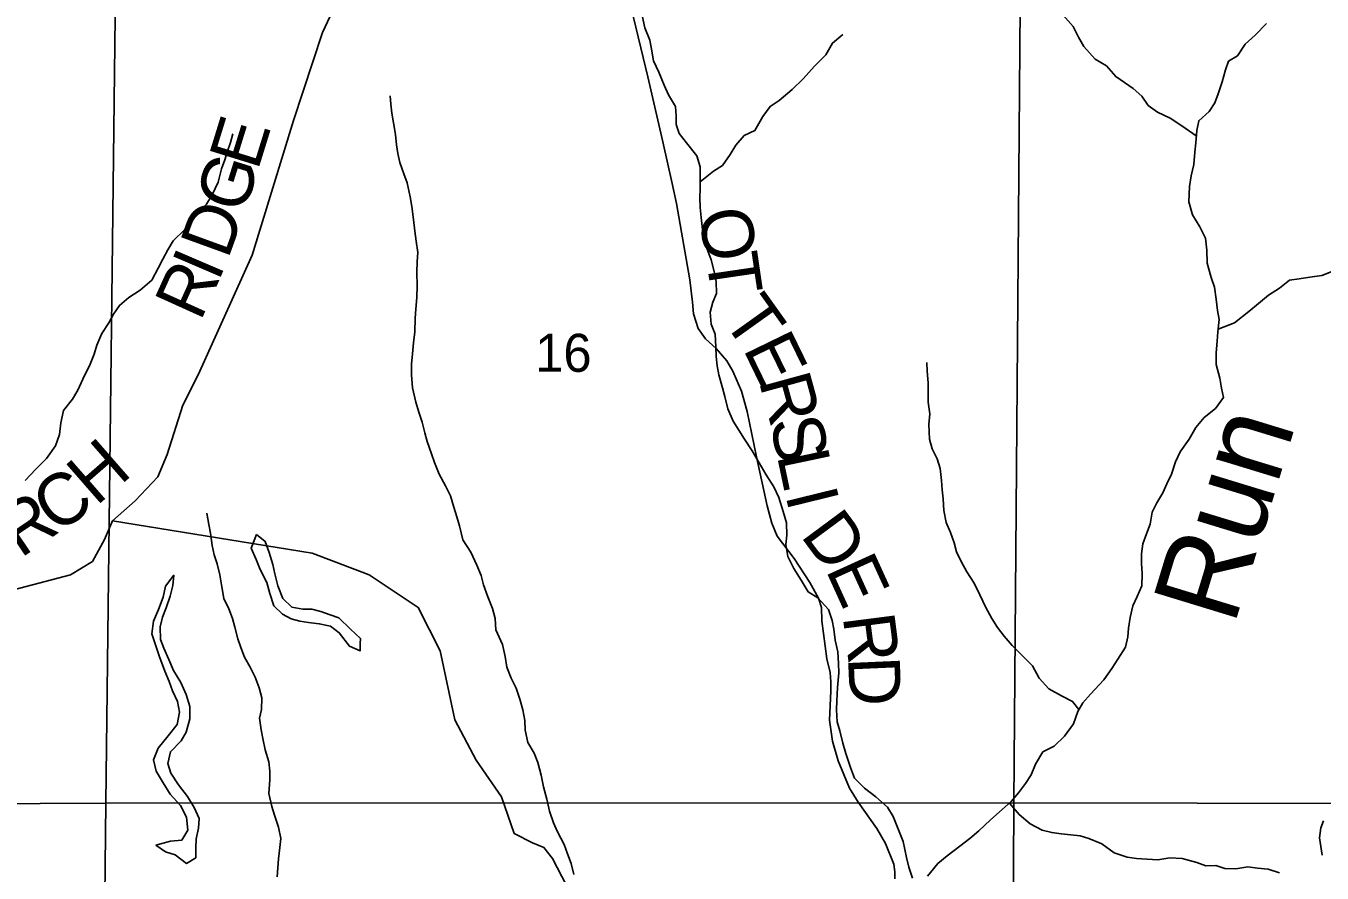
# Model space of a CAD drawing. Extents: x 2043100 to 2470832, y 443715 to 810583.
# Drawn here: x 2269120 to 2276651, y 621804 to 626725 of the extents above; entities that cross this region are included whole.
import ezdxf

# ---------------------------------------------------------------- set-up
doc = ezdxf.new("R2010")
doc.units = 0
for name, color, linetype in [('GM_X_County_Road', 7, 'Continuous'), ('GM_X_County_Road_Text', 7, 'Continuous'), ('GM_X_Minor_Lake', 7, 'Continuous'), ('GM_X_Minor_River', 7, 'Continuous'), ('GM_X_Minor_River_Text', 7, 'Continuous'), ('GM_X_Section', 7, 'Continuous'), ('GM_X_Section_Text', 7, 'Continuous'), ('GM_X_Township_Road', 7, 'Continuous'), ('GM_X_Township_Road_Text', 7, 'Continuous'), ('GM_X_Township_ROW', 7, 'Continuous')]:
    doc.layers.add(name, color=color, linetype=linetype)

msp = doc.modelspace()

# ---------------------------------------------------------------- linework, layer by layer
at = {"layer": 'GM_X_County_Road'}
msp.add_lwpolyline([(2274168.1, 621770.9), (2274169.4, 621811), (2274162.6, 621855), (2274114.4, 621976.4), (2274064.9, 622061.7), (2273956.1, 622216), (2273904.7, 622297.3), (2273839.8, 622456.5), (2273805.8, 622570.1), (2273789.6, 622692.1), (2273796.6, 622860.6), (2273797.6, 622914.7), (2273792.6, 622968.7), (2273773.2, 623048.5), (2273745.3, 623268.5), (2273741.9, 623346.6), (2273724.9, 623400.4), (2273675.3, 623491.7), (2273582.8, 623630.3), (2273484.4, 623760.8), (2273453.1, 623836.4), (2273427.3, 623938.1), (2273364.2, 624221.6), (2273311.5, 624485.2), (2273277.3, 624602.8), (2273227.2, 624720.2), (2273192.2, 624779.6), (2273130.9, 624850.7), (2273067.9, 624907.6), (2273026.8, 624967), (2272999.3, 625052.7), (2272992, 625120.7), (2272977.7, 625250.7), (2272899.8, 625694.2), (2272875.7, 625810), (2272821.4, 626051.5), (2272732.6, 626428.7), (2272637.4, 626829.8)], dxfattribs=at)
at = {"layer": 'GM_X_Minor_Lake'}
for points in [[(2270458.9, 623770.8), (2270429.2, 623690.6), (2270457.5, 623624.6), (2270481.8, 623566.6), (2270520.3, 623492.7), (2270536.6, 623428.6), (2270561, 623356.6), (2270611.3, 623308.8), (2270661.6, 623281), (2270711.7, 623267.2), (2270761.9, 623259.4), (2270824.1, 623251.7), (2270890.3, 623237.9), (2270940.6, 623200.1), (2270999.1, 623122.2), (2271061.4, 623094.5), (2271062.4, 623137.2)], [(2271062.4, 623137.2), (2271063.1, 623166.6), (2271006.7, 623220.4), (2270938.2, 623286.2), (2270888, 623304), (2270833.8, 623323.8), (2270781.6, 623337.6), (2270729.5, 623337.3), (2270665.3, 623349.1), (2270612.9, 623398.9), (2270584.5, 623472.9), (2270566.2, 623542.9), (2270553.9, 623597), (2270533.5, 623667), (2270509.2, 623731), (2270458.9, 623770.8)], [(2270072.4, 622749.4), (2270072.3, 622771.5), (2270051.9, 622841.5), (2270019.5, 622911.5), (2269977.1, 622981.4), (2269950.8, 623045.4), (2269920.4, 623109.4), (2269902.1, 623161.4), (2269899.8, 623233.5), (2269913.6, 623289.6), (2269935.4, 623343.8), (2269957.2, 623412), (2269973, 623474.2), (2269978.7, 623534.3), (2269930.9, 623470), (2269917.1, 623405.8), (2269889.3, 623335.6), (2269861.6, 623267.3), (2269851.9, 623193.2), (2269872.2, 623129.2), (2269896.6, 623059.2), (2269927, 622977.2), (2269951.3, 622917.2), (2269971.6, 622863.2), (2270000, 622801.2), (2270012.3, 622739.2), (2269998.6, 622667), (2269946.7, 622600.7), (2269888.9, 622530.3), (2269861.1, 622462.1), (2269877.4, 622396), (2269917.8, 622328.1), (2269958.2, 622262.2), (2270018.7, 622196.4), (2270053.1, 622128.4), (2270061.4, 622052.3), (2270025.6, 621994.1), (2269959.4, 621989.8), (2269875.3, 621965.4)], [(2269875.3, 621965.4), (2269931.6, 621927.5), (2269987.9, 621909.8), (2270052.2, 621860), (2270106.2, 621892.3), (2270108, 621950.4), (2270109.8, 622002.5), (2270123.5, 622064.6), (2270127.3, 622120.7), (2270096.9, 622184.7), (2270058.6, 622248.6), (2270006.1, 622316.5), (2269961.7, 622384.4), (2269945.4, 622440.4), (2269959.2, 622508.6), (2270021, 622571), (2270050.9, 622623.2), (2270072.6, 622699.4), (2270072.4, 622749.4)]]:
    msp.add_lwpolyline(points, dxfattribs=at)
at = {"layer": 'GM_X_Minor_River'}
for points in [[(2274271.3, 621774.7), (2274249, 621838.7), (2274236.7, 621894.8), (2274216.3, 621986.8), (2274185.8, 622064.8), (2274159.5, 622132.8), (2274125.2, 622186.7), (2274058.7, 622246.5), (2273992.3, 622296.3), (2273933.9, 622354.2), (2273911.6, 622416.2), (2273883.2, 622498.2), (2273866.9, 622558.2), (2273848.5, 622630.2), (2273834.3, 622682.2), (2273829.9, 622752.3), (2273831.7, 622804.4), (2273835.4, 622882.5), (2273843, 622966.7), (2273840.8, 623020.8), (2273836.5, 623088.9), (2273822.1, 623156.9), (2273813.8, 623221), (2273803.6, 623271), (2273783.3, 623335), (2273720.8, 623402.8), (2273664.5, 623436.7), (2273624.1, 623504.6), (2273581.7, 623572.5), (2273547.3, 623642.4), (2273535, 623712.5), (2273540.7, 623766.6), (2273538.4, 623838.7), (2273520.1, 623904.7), (2273493.7, 623984.7), (2273465.3, 624046.7), (2273420.9, 624116.6), (2273340.1, 624256.4), (2273295.7, 624324.3), (2273261.4, 624376.3), (2273229.1, 624428.2), (2273198.7, 624500.2), (2273180.3, 624572.2), (2273168, 624622.2), (2273145.7, 624698.2), (2273135.4, 624750.3), (2273131.2, 624804.3), (2273128.9, 624860.4), (2273124.6, 624934.5), (2273102.3, 624992.5), (2273095.9, 625062.6), (2273111.7, 625120.7), (2273131.5, 625170.9), (2273131.2, 625241), (2273119, 625299), (2273100.6, 625367), (2273076.3, 625435), (2273060, 625493), (2273051.7, 625543.1), (2273043.4, 625613.1), (2273037.1, 625671.2), (2273034.9, 625727.2), (2273036.6, 625781.3), (2273038.3, 625855.4), (2273038.1, 625907.5), (2273017.8, 625971.5), (2272957.3, 626045.4), (2272914.9, 626101.2), (2272898.7, 626153.2), (2272898.4, 626203.3), (2272894.2, 626257.4), (2272853.8, 626325.3), (2272827.5, 626381.3), (2272797.1, 626457.2), (2272766.7, 626523.2), (2272754.4, 626591.2), (2272744.1, 626643.3), (2272715.7, 626715.2), (2272701.4, 626785.3)], [(2275920, 626087.6), (2275836.2, 626144.3), (2275767.8, 626190), (2275695.4, 626223.8), (2275641.1, 626263.6), (2275602.8, 626317.5), (2275552.5, 626361.3), (2275502.2, 626397.1), (2275451.9, 626431), (2275397.5, 626492.8), (2275333.2, 626532.6), (2275266.7, 626606.4), (2275236.4, 626660.3), (2275204, 626722.3), (2275147.6, 626788.1)], [(2273037.5, 625819.7), (2273114.4, 625881.8), (2273166.4, 625914.1), (2273212.2, 625978.4), (2273244.1, 626032.6), (2273293.9, 626088.9), (2273356, 626117.2), (2273401.7, 626199.6), (2273443.6, 626257.8), (2273495.6, 626292.1), (2273571.5, 626356.5), (2273635.4, 626418.9), (2273701.2, 626491.3), (2273767.1, 626557.7), (2273806.9, 626626), (2273866.8, 626676.3)], [(2275602.7, 623601.5), (2275602.5, 623657.6), (2275610.2, 623715.7), (2275630, 623773.9), (2275651.8, 623830.1), (2275663.6, 623900.2), (2275691.4, 623954.4), (2275725.2, 624012.7), (2275749, 624064.9), (2275776.9, 624121.1), (2275798.6, 624193.3), (2275826.4, 624251.5), (2275878.2, 624323.8), (2275918, 624392.1), (2275965.9, 624450.4), (2276031.8, 624502.8), (2276077.7, 624567.1), (2276067.4, 624621.1), (2276057.1, 624679.2), (2276034.7, 624759.2), (2276036.4, 624825.3), (2276042.2, 624893.4), (2276045.9, 624947.5), (2276053.6, 625019.6), (2276043.4, 625071.7), (2276035.1, 625137.7), (2276026.7, 625207.8), (2276006.4, 625263.8), (2275984, 625347.8), (2275981.7, 625421.9), (2275973.4, 625491.9), (2275941, 625557.9), (2275898.6, 625627.8), (2275876.2, 625703.8), (2275879.8, 625792), (2275889.6, 625854.1), (2275905.3, 625920.3), (2275911, 625992.4), (2275916.8, 626046.5), (2275922.5, 626118.6), (2275934.3, 626174.7), (2275994.2, 626229.1), (2276028, 626279.3), (2276047.9, 626331.5), (2276069.6, 626399.7), (2276089.4, 626469.8), (2276107.2, 626520), (2276159.2, 626552.3), (2276205, 626618.5), (2276262.9, 626670.9), (2276328.8, 626739.3)], [(2272304.2, 621796), (2272287.9, 621860), (2272267.6, 621916), (2272247.3, 621970), (2272208.9, 622043.9), (2272184.6, 622095.9), (2272162.3, 622163.9), (2272145.9, 622234), (2272127.6, 622304), (2272113.2, 622372), (2272094.9, 622446.1), (2272072.6, 622500.1), (2272036.2, 622562), (2272019.8, 622634), (2272019.6, 622690.1), (2272007.3, 622752.2), (2271989, 622814.2), (2271968.7, 622878.2), (2271940.3, 622936.2), (2271914, 623000.1), (2271903.7, 623062.2), (2271889.3, 623132.2), (2271850.9, 623216.2), (2271846.6, 623282.3), (2271830.3, 623340.3), (2271803.9, 623408.3), (2271779.5, 623478.3), (2271765.3, 623532.3), (2271738.9, 623592.3), (2271704.5, 623668.2), (2271658.1, 623740.1), (2271639.7, 623820.2), (2271623.4, 623874.2), (2271607.1, 623930.2), (2271586.8, 623996.2), (2271558.4, 624054.2), (2271520.1, 624122.1), (2271493.7, 624188.1), (2271477.4, 624240.1), (2271451, 624310.1), (2271436.8, 624362.1), (2271422.5, 624424.1), (2271402.2, 624482.1), (2271385.9, 624540.1), (2271365.5, 624622.2), (2271361.1, 624698.2), (2271360.8, 624760.3), (2271366.6, 624820.5), (2271372.3, 624884.6), (2271380.1, 624948.7), (2271381.7, 625026.8), (2271385.5, 625078.9), (2271391.2, 625147), (2271392.9, 625215.2), (2271390.6, 625293.3), (2271392.3, 625357.4), (2271396.1, 625409.5), (2271387.8, 625475.5), (2271379.5, 625533.6), (2271371.2, 625601.6), (2271362.8, 625675.7), (2271352.6, 625731.7), (2271334.2, 625813.8), (2271315.9, 625865.8), (2271291.5, 625931.8), (2271281.3, 625983.8), (2271273, 626033.8), (2271266.8, 626093.9), (2271256.4, 626161.9), (2271246.2, 626218), (2271239.9, 626270), (2271235.7, 626320.1)], [(2270274.9, 625947.2), (2270290.7, 625997.4), (2270308.5, 626047.5), (2270322.3, 626097.7)], [(2269116.1, 624085.3), (2269178, 624149.6), (2269239.8, 624212), (2269291.7, 624286.3), (2269315.4, 624352.6), (2269323.2, 624418.7), (2269338.9, 624490.9), (2269390.7, 624557.2), (2269420.6, 624609.4), (2269460.3, 624693.7), (2269490.1, 624749.9), (2269515.9, 624818.2), (2269531.7, 624870.3), (2269561.5, 624938.5), (2269601.3, 625000.8), (2269629.2, 625051), (2269663, 625101.2), (2269717, 625147.5), (2269782.9, 625189.9), (2269850.9, 625248.3), (2269888.7, 625318.6), (2269914.5, 625370.8), (2269944.3, 625425), (2269976.2, 625477.2), (2270044.1, 625543.6), (2270103.9, 625618), (2270169.7, 625690.4), (2270201.6, 625744.6), (2270237.4, 625816.9), (2270257.1, 625895.1), (2270274.9, 625947.2)], [(2276047.6, 624963.3), (2276141.9, 625000), (2276225.9, 625066.5), (2276281.8, 625112.8), (2276339.7, 625161.1), (2276403.7, 625201.4), (2276461.7, 625247.8), (2276517.8, 625256), (2276579.9, 625266.3), (2276650, 625274.6), (2276714.1, 625300.9)], [(2275237.9, 622753.2), (2275201.2, 622800.5), (2275136.9, 622834.3), (2275062.5, 622874), (2275008.1, 622935.9), (2274967.7, 623007.8), (2274901.2, 623075.6), (2274850.9, 623125.5), (2274804.5, 623179.3), (2274764.2, 623231.2), (2274731.9, 623283.2), (2274697.5, 623347.1), (2274663.1, 623421.1), (2274628.7, 623487), (2274586.3, 623552.9), (2274554, 623612.9), (2274527.7, 623670.9), (2274513.4, 623722.9), (2274491.1, 623782.9), (2274466.8, 623840.8), (2274452.4, 623910.9), (2274450.1, 623977), (2274443.9, 624031), (2274439.6, 624085.1), (2274431.3, 624153.2), (2274415, 624211.2), (2274384.7, 624269.1), (2274370.4, 624325.1), (2274366, 624409.2), (2274371.8, 624471.4), (2274361.4, 624539.4), (2274363.2, 624595.5), (2274363, 624651.6), (2274356.6, 624719.7), (2274354.4, 624769.7)], [(2270579.9, 621782.2), (2270587.5, 621886.4), (2270595.2, 621952.6), (2270601, 622004.7), (2270586.7, 622070.7), (2270564.3, 622140.7), (2270548.1, 622190.7), (2270531.7, 622266.8), (2270537.3, 622344.9), (2270537.1, 622395), (2270530.9, 622449.1), (2270510.5, 622519.1), (2270496.2, 622585.1), (2270485.9, 622635.2), (2270477.6, 622703.2), (2270489.4, 622753.4), (2270491.1, 622821.5), (2270474.8, 622879.5), (2270452.5, 622941.5), (2270422.2, 622999.4), (2270389.8, 623057.4), (2270369.5, 623113.4), (2270351.3, 623165.4), (2270332.9, 623231.4), (2270320.7, 623283.4), (2270298.4, 623339.4), (2270270, 623399.4), (2270257.7, 623467.4), (2270247.4, 623535.5), (2270231.1, 623599.5), (2270212.8, 623653.5), (2270202.5, 623707.6), (2270192.2, 623777.6), (2270181.9, 623829.7), (2270171.6, 623893.7)], [(2274357.5, 621785.1), (2274419.3, 621859.5), (2274473.3, 621903.8), (2274547.2, 621960.2), (2274605.2, 622004.6), (2274657.1, 622048.9), (2274725, 622113.3), (2274792.9, 622173.7), (2274844.8, 622220), (2274886.7, 622270.3), (2274928.6, 622324.5), (2274960.5, 622374.8), (2274986.2, 622437), (2275028, 622507.3), (2275094.1, 622541.6), (2275154, 622600), (2275205.8, 622670.3), (2275231.5, 622742.5), (2275261.4, 622792.8), (2275305.3, 622843), (2275383.1, 622925.5), (2275428.9, 622991.8), (2275464.8, 623046.1), (2275508.6, 623116.4), (2275522.4, 623176.5), (2275526.2, 623226.6), (2275535.9, 623288.8), (2275551.6, 623356.9), (2275577.5, 623411.1), (2275603.3, 623473.3), (2275605, 623543.4), (2275602.7, 623601.5)], [(2274834.1, 622210.4), (2274891.3, 622144.1), (2274955.7, 622090.3), (2275024, 622052.5), (2275080.2, 622038.8), (2275134.4, 622031), (2275190.6, 622025.2), (2275244.7, 622019.4), (2275294.9, 622003.7), (2275371.3, 621973.9), (2275443.7, 621922.2), (2275518, 621896.5), (2275572.1, 621888.7), (2275696.5, 621881.2), (2275766.6, 621891.6), (2275838.8, 621887.9), (2275923.1, 621864.2), (2275975.4, 621846.4), (2276033.5, 621846.7), (2276085.7, 621830.9), (2276149.9, 621829.2), (2276220, 621839.5), (2276276.2, 621831.7), (2276338.4, 621826), (2276404.6, 621804.3)]]:
    msp.add_lwpolyline(points, dxfattribs=at)
at = {"layer": 'GM_X_Section'}
for points in [[(2269648.4, 627594.9), (2269583.7, 622209.9), (2264235.8, 622182.9), (2264250.8, 627533.3)], [(2269648.4, 627594.9), (2274902.9, 627568.7), (2274859.9, 622212), (2269583.7, 622209.9)], [(2280223.7, 627519.3), (2280184.2, 622202.6), (2274859.9, 622212), (2274902.9, 627568.7)], [(2264235.8, 622182.9), (2269583.7, 622209.9), (2269527.4, 616965), (2264207.2, 616970.4)], [(2274859.9, 622212), (2274832.1, 616923.4), (2269527.4, 616965), (2269583.7, 622209.9)], [(2274859.9, 622212), (2280184.2, 622202.6), (2280154.7, 616890), (2274832.1, 616923.4)]]:
    msp.add_lwpolyline(points, close=True, dxfattribs=at)
at = {"layer": 'GM_X_Township_Road'}
for points in [[(2270917.1, 626845), (2270843, 626687.6), (2270675.3, 626176), (2270434.9, 625392.7), (2270121.2, 624698.7), (2270031.3, 624523), (2269940.9, 624235), (2269886.4, 624106), (2269754, 623965.8), (2269622.3, 623849.5), (2269576.6, 623740.8), (2269506.1, 623613.5), (2269378.9, 623535.6), (2269011.5, 623440.4)], [(2276659.5, 622107.3), (2276644, 622067), (2276636.8, 622008.7), (2276652.1, 621908.6)]]:
    msp.add_lwpolyline(points, dxfattribs=at)
at = {"layer": 'GM_X_Township_ROW'}
msp.add_lwpolyline([(2272793.9, 620983.6), (2272793.7, 620983.8), (2272771, 621008.1), (2272685.7, 621103.2), (2272599.9, 621226.4), (2272406, 621504.6), (2272297.8, 621663.6), (2272234.2, 621783.1), (2272178.7, 621888.6), (2272129.8, 621952.1), (2272063.4, 621979.3), (2271956.5, 622034), (2271883.7, 622245.7), (2271736.7, 622460.3), (2271611.5, 622693.3), (2271525.9, 623094.1), (2271399.4, 623346.9), (2271115.1, 623536.5), (2270783.3, 623662.8), (2269622.3, 623849.5)], dxfattribs=at)

# ---------------------------------------------------------------- texts
at = {"layer": 'GM_X_County_Road_Text'}
for s, rotation, p in [('O', 279.94384, (2273024.7, 625644.6)), ('T', 278.37799, (2273070, 625386.7)), ('T', 305.52313, (2273160.2, 625022.1)), ('E', 295.93449, (2273283.8, 624850.9)), ('R', 285.31332, (2273376.7, 624662.8)), ('S', 281.91656, (2273440.7, 624429.7)), ('L', 281.92079, (2273482.5, 624231.7)), ('I', 283.80115, (2273531.3, 624001.6)), ('D', 306.51588, (2273615.5, 623765.2)), ('E', 294.46595, (2273764.2, 623567.3)), ('R', 277.33028, (2273865.3, 623294.6)), ('D', 272.52896, (2273896.2, 623056.8))]:
    msp.add_text(s, height=300, rotation=rotation, dxfattribs=at).set_placement(p)
at = {"layer": 'GM_X_Minor_River_Text'}
msp.add_text('Run', height=500.02, rotation=73.00708, dxfattribs=at).set_placement((2276139.2, 623234.4))
at = {"layer": 'GM_X_Section_Text'}
msp.add_text('16', height=220.83, rotation=0.00001, dxfattribs=at).set_placement((2272078.4, 624715.8))
at = {"layer": 'GM_X_Township_Road_Text'}
for s, rotation, p in [('E', 72.79137, (2270466.4, 625879.4)), ('G', 72.7137, (2270387.9, 625626.9)), ('D', 70.00929, (2270292.7, 625364.1)), ('I', 66.78171, (2270237.3, 625233.7)), ('R', 65.63647, (2270133, 625003.3)), ('H', 41.1347, (2269527.9, 623931.2)), ('C', 34.27826, (2269293.3, 623768.4)), ('R', 34.04838, (2269088, 623629.8))]:
    msp.add_text(s, height=300, rotation=rotation, dxfattribs=at).set_placement(p)

doc.saveas('drawing.dxf')
